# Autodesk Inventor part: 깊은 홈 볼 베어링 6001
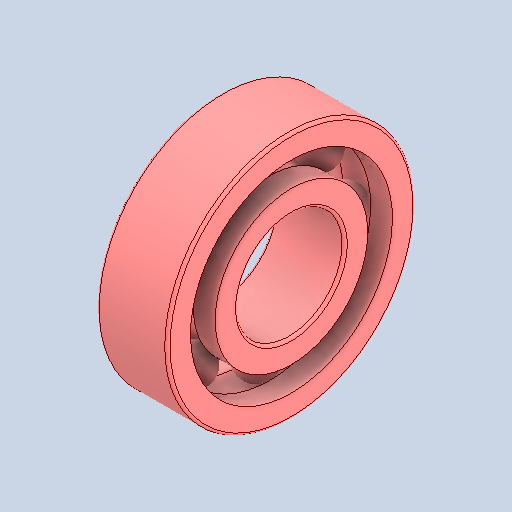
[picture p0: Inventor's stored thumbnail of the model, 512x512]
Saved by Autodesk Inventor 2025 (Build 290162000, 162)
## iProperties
Created: 2026-07
Part Number: 깊은 홈 볼 베어링 6001
Material: 강철, 연강
Description: 깊은 그루브 볼 베어링
Document SubType Name: Modeling
Designer: KDI
Density: 7.85 g/cm^3
Appearance: 기본값
Author: jhkim
Sending System: Autodesk Inventor 2027
Preprocessor: ST-DEVELOPER v20.1
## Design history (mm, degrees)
feature "Solid1"
feature "Solid1:1"
feature "Solid1:2"
feature "Solid1:3"
feature "Solid1:4"
feature "Solid1:5"
feature "Solid1:6"
feature "Solid1:7"
feature "Solid1:8"
feature "Solid1:9"
node "솔리드1"
node "솔리드2"
node "솔리드3"
node "솔리드4"
node "솔리드5"
node "솔리드6"
node "솔리드7"
node "솔리드8"
node "솔리드9"
node "솔리드10"
